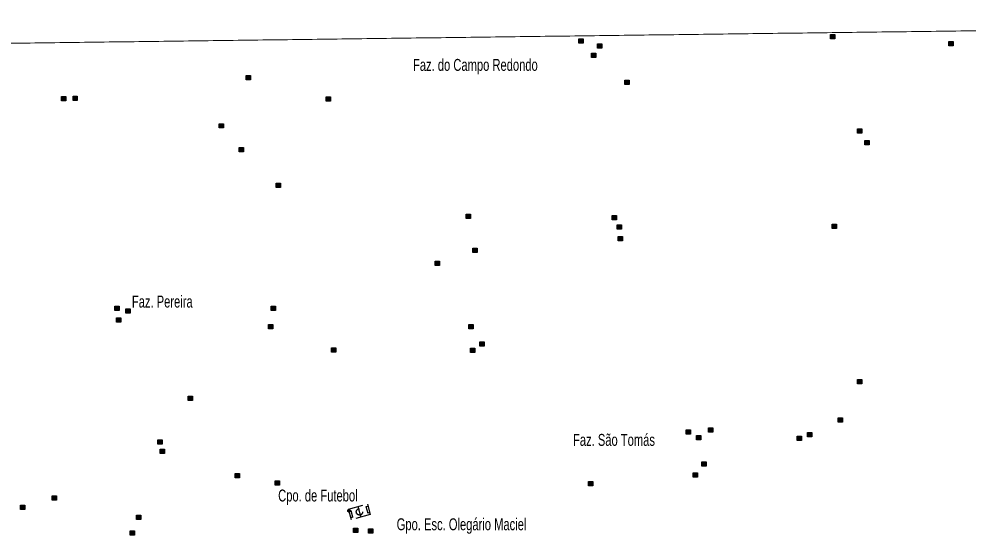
# Model space of a CAD drawing. Extents: x 265.7 to 292.1, y 7676.2 to 7704.2.
# Drawn here: x 279.03 to 285.4, y 7700.74 to 7704.2 of the extents above; entities that cross this region are included whole.
import ezdxf

# ---------------------------------------------------------------- set-up
doc = ezdxf.new("R2010")
doc.units = 0
doc.header["$LTSCALE"] = 0.032
doc.header["$PDMODE"] = 32
doc.header["$PDSIZE"] = 0.016
doc.linetypes.add('MEDIUM_DASHED', pattern=[4.5, 3, -1.5])
for name, color, linetype, lineweight in [('14', 7, 'MEDIUM_DASHED', 25), ('2', 7, 'Continuous', 25), ('63', 7, 'Continuous', 13)]:
    doc.layers.add(name, color=color, linetype=linetype, lineweight=lineweight)
doc.layers.add('61', color=7, linetype='Continuous')

msp = doc.modelspace()

# ---------------------------------------------------------------- hatches: boundary and pattern name
at = {"layer": '2'}
for points in [[(282.7855, 7704.0704), (282.8145, 7704.0704), (282.8145, 7704.0414), (282.7855, 7704.0414)], [(284.473, 7704.0979), (284.502, 7704.0979), (284.502, 7704.0689), (284.473, 7704.0689)], [(285.2655, 7704.0511), (285.2945, 7704.0511), (285.2945, 7704.0221), (285.2655, 7704.0221)], [(282.9108, 7704.0366), (282.9398, 7704.0366), (282.9398, 7704.0076), (282.9108, 7704.0076)], [(282.869, 7703.973), (282.898, 7703.973), (282.898, 7703.944), (282.869, 7703.944)], [(280.5523, 7703.8234), (280.5813, 7703.8234), (280.5813, 7703.7944), (280.5523, 7703.7944)], [(283.0929, 7703.792), (283.1219, 7703.792), (283.1219, 7703.763), (283.0929, 7703.763)], [(279.3143, 7703.6839), (279.3433, 7703.6839), (279.3433, 7703.6549), (279.3143, 7703.6549)], [(279.3918, 7703.6854), (279.4208, 7703.6854), (279.4208, 7703.6564), (279.3918, 7703.6564)], [(281.0898, 7703.6798), (281.1188, 7703.6798), (281.1188, 7703.6508), (281.0898, 7703.6508)], [(280.3732, 7703.5007), (280.4022, 7703.5007), (280.4022, 7703.4717), (280.3732, 7703.4717)], [(284.6537, 7703.4652), (284.6827, 7703.4652), (284.6827, 7703.4362), (284.6537, 7703.4362)], [(284.703, 7703.3885), (284.732, 7703.3885), (284.732, 7703.3595), (284.703, 7703.3595)], [(280.5072, 7703.3409), (280.5362, 7703.3409), (280.5362, 7703.3119), (280.5072, 7703.3119)], [(280.7549, 7703.102), (280.7839, 7703.102), (280.7839, 7703.073), (280.7549, 7703.073)], [(282.03, 7702.8938), (282.059, 7702.8938), (282.059, 7702.8648), (282.03, 7702.8648)], [(283.0091, 7702.8857), (283.0381, 7702.8857), (283.0381, 7702.8567), (283.0091, 7702.8567)], [(283.0421, 7702.8219), (283.0711, 7702.8219), (283.0711, 7702.7929), (283.0421, 7702.7929)], [(284.4835, 7702.8276), (284.5125, 7702.8276), (284.5125, 7702.7986), (284.4835, 7702.7986)], [(283.0494, 7702.7436), (283.0784, 7702.7436), (283.0784, 7702.7146), (283.0494, 7702.7146)], [(282.0737, 7702.6645), (282.1027, 7702.6645), (282.1027, 7702.6355), (282.0737, 7702.6355)], [(281.8213, 7702.5774), (281.8503, 7702.5774), (281.8503, 7702.5484), (281.8213, 7702.5484)], [(279.6734, 7702.2763), (279.7024, 7702.2763), (279.7024, 7702.2473), (279.6734, 7702.2473)], [(280.7219, 7702.2771), (280.7509, 7702.2771), (280.7509, 7702.2481), (280.7219, 7702.2481)], [(279.7469, 7702.2594), (279.7759, 7702.2594), (279.7759, 7702.2304), (279.7469, 7702.2304)], [(279.684, 7702.1989), (279.713, 7702.1989), (279.713, 7702.1699), (279.684, 7702.1699)], [(280.7033, 7702.1546), (280.7323, 7702.1546), (280.7323, 7702.1256), (280.7033, 7702.1256)], [(282.0462, 7702.1546), (282.0752, 7702.1546), (282.0752, 7702.1256), (282.0462, 7702.1256)], [(282.1205, 7702.0382), (282.1495, 7702.0382), (282.1495, 7702.0092), (282.1205, 7702.0092)], [(281.1254, 7701.9972), (281.1544, 7701.9972), (281.1544, 7701.9682), (281.1254, 7701.9682)], [(282.0576, 7701.9948), (282.0866, 7701.9948), (282.0866, 7701.9658), (282.0576, 7701.9658)], [(284.6529, 7701.784), (284.6819, 7701.784), (284.6819, 7701.755), (284.6529, 7701.755)], [(280.1641, 7701.6719), (280.1931, 7701.6719), (280.1931, 7701.6429), (280.1641, 7701.6429)], [(284.5238, 7701.5283), (284.5528, 7701.5283), (284.5528, 7701.4993), (284.5238, 7701.4993)], [(283.5037, 7701.4467), (283.5327, 7701.4467), (283.5327, 7701.4177), (283.5037, 7701.4177)], [(283.6546, 7701.4613), (283.6836, 7701.4613), (283.6836, 7701.4323), (283.6546, 7701.4323)], [(279.9615, 7701.379), (279.9905, 7701.379), (279.9905, 7701.35), (279.9615, 7701.35)], [(283.5747, 7701.4096), (283.6037, 7701.4096), (283.6037, 7701.3806), (283.5747, 7701.3806)], [(284.2486, 7701.4055), (284.2776, 7701.4055), (284.2776, 7701.3765), (284.2486, 7701.3765)], [(284.3189, 7701.4282), (284.3479, 7701.4282), (284.3479, 7701.3992), (284.3189, 7701.3992)], [(279.977, 7701.3169), (280.006, 7701.3169), (280.006, 7701.2879), (279.977, 7701.2879)], [(283.6095, 7701.2321), (283.6385, 7701.2321), (283.6385, 7701.2031), (283.6095, 7701.2031)], [(280.4806, 7701.1538), (280.5096, 7701.1538), (280.5096, 7701.1248), (280.4806, 7701.1248)], [(283.5513, 7701.1586), (283.5803, 7701.1586), (283.5803, 7701.1296), (283.5513, 7701.1296)], [(280.7484, 7701.1053), (280.7774, 7701.1053), (280.7774, 7701.0763), (280.7484, 7701.0763)], [(282.85, 7701.1013), (282.879, 7701.1013), (282.879, 7701.0723), (282.85, 7701.0723)], [(279.2529, 7701.0036), (279.2819, 7701.0036), (279.2819, 7700.9746), (279.2529, 7700.9746)], [(279.0399, 7700.9406), (279.0689, 7700.9406), (279.0689, 7700.9116), (279.0399, 7700.9116)], [(279.8179, 7700.8745), (279.8469, 7700.8745), (279.8469, 7700.8455), (279.8179, 7700.8455)], [(279.7752, 7700.7704), (279.8042, 7700.7704), (279.8042, 7700.7414), (279.7752, 7700.7414)], [(281.2731, 7700.7874), (281.3021, 7700.7874), (281.3021, 7700.7584), (281.2731, 7700.7584)], [(281.3739, 7700.7834), (281.4029, 7700.7834), (281.4029, 7700.7544), (281.3739, 7700.7544)]]:
    msp.add_hatch(color=256, dxfattribs=at).paths.add_polyline_path(points)

# ---------------------------------------------------------------- linework, layer by layer
at = {"layer": '14'}
for p, q in [((281.3032, 7700.9317), (281.3229, 7700.8613)), ((281.3565, 7700.9317), (281.3702, 7700.9356)), ((281.3565, 7700.9317), (281.3684, 7700.8889)), ((281.2428, 7700.9039), (281.2429, 7700.9039)), ((281.2439, 7700.9003), (281.2577, 7700.9042)), ((281.2696, 7700.8614), (281.2577, 7700.9042)), ((281.3822, 7700.8927), (281.3684, 7700.8889)), ((281.2554, 7700.8593), (281.2551, 7700.8589)), ((281.2696, 7700.8614), (281.2558, 7700.8575))]:
    msp.add_line(p, q, dxfattribs=at)
msp.add_lwpolyline([(281.2597, 7700.8438), (281.24, 7700.9141), (281.3664, 7700.9494), (281.386, 7700.8789)], close=True, dxfattribs=at)
msp.add_circle((281.3131, 7700.8965), 0.0212, dxfattribs=at)
msp.add_point((281.2429, 7700.9036), dxfattribs=at)
at = {"layer": '2'}
for points in [[(282.7855, 7704.0704), (282.8145, 7704.0704), (282.8145, 7704.0414), (282.7855, 7704.0414)], [(284.473, 7704.0979), (284.502, 7704.0979), (284.502, 7704.0689), (284.473, 7704.0689)], [(285.2655, 7704.0511), (285.2945, 7704.0511), (285.2945, 7704.0221), (285.2655, 7704.0221)], [(282.9108, 7704.0366), (282.9398, 7704.0366), (282.9398, 7704.0076), (282.9108, 7704.0076)], [(282.869, 7703.973), (282.898, 7703.973), (282.898, 7703.944), (282.869, 7703.944)], [(280.5523, 7703.8234), (280.5813, 7703.8234), (280.5813, 7703.7944), (280.5523, 7703.7944)], [(283.0929, 7703.792), (283.1219, 7703.792), (283.1219, 7703.763), (283.0929, 7703.763)], [(279.3143, 7703.6839), (279.3433, 7703.6839), (279.3433, 7703.6549), (279.3143, 7703.6549)], [(279.3918, 7703.6854), (279.4208, 7703.6854), (279.4208, 7703.6564), (279.3918, 7703.6564)], [(281.0898, 7703.6798), (281.1188, 7703.6798), (281.1188, 7703.6508), (281.0898, 7703.6508)], [(280.3732, 7703.5007), (280.4022, 7703.5007), (280.4022, 7703.4717), (280.3732, 7703.4717)], [(284.6537, 7703.4652), (284.6827, 7703.4652), (284.6827, 7703.4362), (284.6537, 7703.4362)], [(284.703, 7703.3885), (284.732, 7703.3885), (284.732, 7703.3595), (284.703, 7703.3595)], [(280.5072, 7703.3409), (280.5362, 7703.3409), (280.5362, 7703.3119), (280.5072, 7703.3119)], [(280.7549, 7703.102), (280.7839, 7703.102), (280.7839, 7703.073), (280.7549, 7703.073)], [(282.03, 7702.8938), (282.059, 7702.8938), (282.059, 7702.8648), (282.03, 7702.8648)], [(283.0091, 7702.8857), (283.0381, 7702.8857), (283.0381, 7702.8567), (283.0091, 7702.8567)], [(283.0421, 7702.8219), (283.0711, 7702.8219), (283.0711, 7702.7929), (283.0421, 7702.7929)], [(284.4835, 7702.8276), (284.5125, 7702.8276), (284.5125, 7702.7986), (284.4835, 7702.7986)], [(283.0494, 7702.7436), (283.0784, 7702.7436), (283.0784, 7702.7146), (283.0494, 7702.7146)], [(282.0737, 7702.6645), (282.1027, 7702.6645), (282.1027, 7702.6355), (282.0737, 7702.6355)], [(281.8213, 7702.5774), (281.8503, 7702.5774), (281.8503, 7702.5484), (281.8213, 7702.5484)], [(279.6734, 7702.2763), (279.7024, 7702.2763), (279.7024, 7702.2473), (279.6734, 7702.2473)], [(280.7219, 7702.2771), (280.7509, 7702.2771), (280.7509, 7702.2481), (280.7219, 7702.2481)], [(279.7469, 7702.2594), (279.7759, 7702.2594), (279.7759, 7702.2304), (279.7469, 7702.2304)], [(279.684, 7702.1989), (279.713, 7702.1989), (279.713, 7702.1699), (279.684, 7702.1699)], [(280.7033, 7702.1546), (280.7323, 7702.1546), (280.7323, 7702.1256), (280.7033, 7702.1256)], [(282.0462, 7702.1546), (282.0752, 7702.1546), (282.0752, 7702.1256), (282.0462, 7702.1256)], [(282.1205, 7702.0382), (282.1495, 7702.0382), (282.1495, 7702.0092), (282.1205, 7702.0092)], [(281.1254, 7701.9972), (281.1544, 7701.9972), (281.1544, 7701.9682), (281.1254, 7701.9682)], [(282.0576, 7701.9948), (282.0866, 7701.9948), (282.0866, 7701.9658), (282.0576, 7701.9658)], [(284.6529, 7701.784), (284.6819, 7701.784), (284.6819, 7701.755), (284.6529, 7701.755)], [(280.1641, 7701.6719), (280.1931, 7701.6719), (280.1931, 7701.6429), (280.1641, 7701.6429)], [(284.5238, 7701.5283), (284.5528, 7701.5283), (284.5528, 7701.4993), (284.5238, 7701.4993)], [(283.5037, 7701.4467), (283.5327, 7701.4467), (283.5327, 7701.4177), (283.5037, 7701.4177)], [(283.6546, 7701.4613), (283.6836, 7701.4613), (283.6836, 7701.4323), (283.6546, 7701.4323)], [(279.9615, 7701.379), (279.9905, 7701.379), (279.9905, 7701.35), (279.9615, 7701.35)], [(283.5747, 7701.4096), (283.6037, 7701.4096), (283.6037, 7701.3806), (283.5747, 7701.3806)], [(284.2486, 7701.4055), (284.2776, 7701.4055), (284.2776, 7701.3765), (284.2486, 7701.3765)], [(284.3189, 7701.4282), (284.3479, 7701.4282), (284.3479, 7701.3992), (284.3189, 7701.3992)], [(279.977, 7701.3169), (280.006, 7701.3169), (280.006, 7701.2879), (279.977, 7701.2879)], [(283.6095, 7701.2321), (283.6385, 7701.2321), (283.6385, 7701.2031), (283.6095, 7701.2031)], [(280.4806, 7701.1538), (280.5096, 7701.1538), (280.5096, 7701.1248), (280.4806, 7701.1248)], [(283.5513, 7701.1586), (283.5803, 7701.1586), (283.5803, 7701.1296), (283.5513, 7701.1296)], [(280.7484, 7701.1053), (280.7774, 7701.1053), (280.7774, 7701.0763), (280.7484, 7701.0763)], [(282.85, 7701.1013), (282.879, 7701.1013), (282.879, 7701.0723), (282.85, 7701.0723)], [(279.2529, 7701.0036), (279.2819, 7701.0036), (279.2819, 7700.9746), (279.2529, 7700.9746)], [(279.0399, 7700.9406), (279.0689, 7700.9406), (279.0689, 7700.9116), (279.0399, 7700.9116)], [(279.8179, 7700.8745), (279.8469, 7700.8745), (279.8469, 7700.8455), (279.8179, 7700.8455)], [(279.7752, 7700.7704), (279.8042, 7700.7704), (279.8042, 7700.7414), (279.7752, 7700.7414)], [(281.2731, 7700.7874), (281.3021, 7700.7874), (281.3021, 7700.7584), (281.2731, 7700.7584)], [(281.3739, 7700.7834), (281.4029, 7700.7834), (281.4029, 7700.7544), (281.3739, 7700.7544)]]:
    msp.add_lwpolyline(points, close=True, dxfattribs=at)
at = {"layer": '63'}
msp.add_spline([(265.7179, 7703.8606), (266.2494, 7703.868), (266.7808, 7703.8754), (267.3123, 7703.8828), (267.8437, 7703.8901), (268.3752, 7703.8974), (268.9066, 7703.9047), (269.4381, 7703.912), (269.9695, 7703.9193), (270.501, 7703.9265), (271.0324, 7703.9338), (271.5639, 7703.941), (272.0953, 7703.9482), (272.6268, 7703.9554), (273.1582, 7703.9626), (273.6896, 7703.9697), (274.2211, 7703.9769), (274.7525, 7703.984), (275.2839, 7703.9911), (275.8154, 7703.9982), (276.3468, 7704.0052), (276.8782, 7704.0123), (277.4097, 7704.0193), (277.9411, 7704.0263), (278.4725, 7704.0333), (279.0039, 7704.0403), (279.5354, 7704.0473), (280.0668, 7704.0543), (280.5982, 7704.0612), (281.1296, 7704.0681), (281.661, 7704.075), (282.1925, 7704.0819), (282.7239, 7704.0888), (283.2553, 7704.0956), (283.7867, 7704.1025), (284.3181, 7704.1093), (284.8495, 7704.1161), (285.3809, 7704.1229), (285.9123, 7704.1296), (286.4437, 7704.1364), (286.9751, 7704.1431), (287.5065, 7704.1498), (288.0379, 7704.1565), (288.5693, 7704.1632), (289.1007, 7704.1699), (289.6321, 7704.1765), (290.1635, 7704.1832), (290.6949, 7704.1898), (291.2263, 7704.1964), (291.7577, 7704.203)], degree=3, dxfattribs=at)

# ---------------------------------------------------------------- texts
at = {"layer": '61', "width": 0.7}
for s, p in [('Faz. do Campo Redondo', (281.6724, 7703.855)), ('Faz. Pereira', (279.7867, 7702.2674)), ('Faz. São Tomás', (282.7458, 7701.3396)), ('Cpo. de Futebol', (280.7679, 7700.9663)), ('Gpo. Esc. Olegário Maciel', (281.563, 7700.7735))]:
    msp.add_text(s, height=0.08, dxfattribs=at).set_placement(p)

doc.saveas('drawing.dxf')
